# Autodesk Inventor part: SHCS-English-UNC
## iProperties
Author: Neil Munro
Shininess: 48.0
PropertySet Name: _Private Model Information
Created: 2001-02
Part Number: SHCS-English-UNC
Material: Steel, Mild
Document SubType Name: Modeling
Designer: Administrator
Control State: 0
Master: False
Checked Out: False
PropertySet Name: Design Tracking Control
Density: 7.86
Volumn: 0.4698874259452923
Area: 5.082331744338173
PropertySet Name: Model Information
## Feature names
1. Body [Extrusion]
2. Head [Extrusion]
3. Hex [Extrusion]
4. Chamfer1
